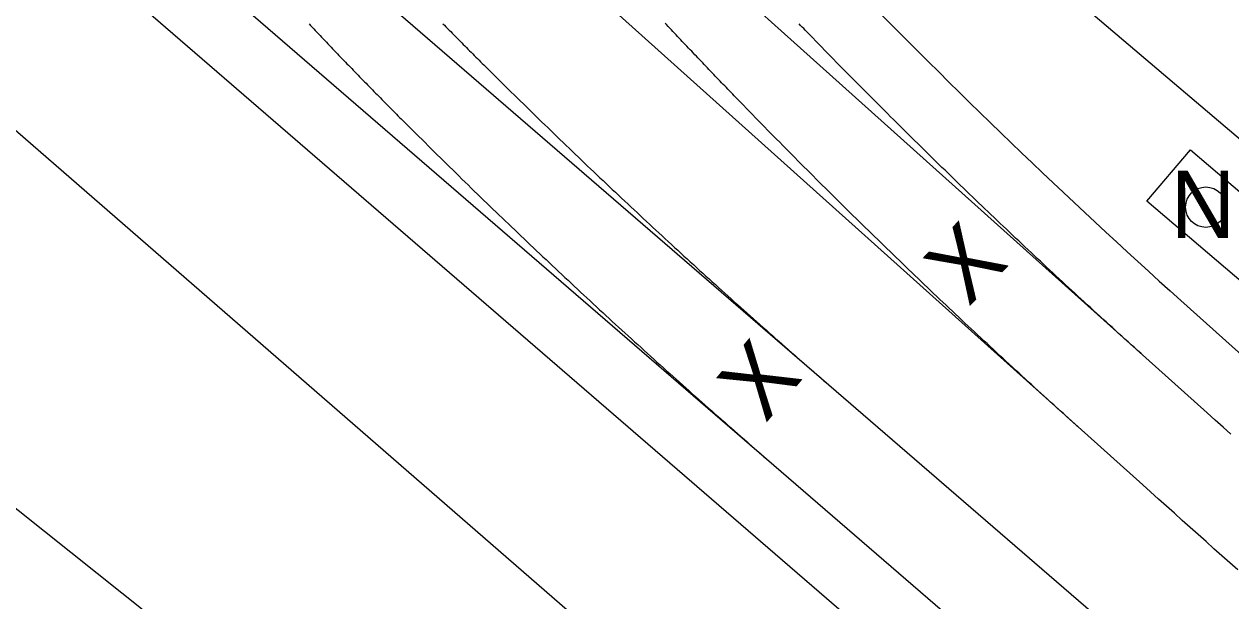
# Model space of a CAD drawing. Extents: x 81617 to 82144, y 454649 to 455150.
# Drawn here: x 81715.37 to 81733.29, y 454706.31 to 454714.88 of the extents above; entities that cross this region are included whole.
import ezdxf

# ---------------------------------------------------------------- set-up
doc = ezdxf.new("R2010")
doc.units = 0
doc.layers.add('B-WE-OG-TOPOGRAFIE-G', color=7, linetype='Continuous')
doc.layers.add('B-WE-VW-MARKERING-G', color=7, linetype='Continuous')

msp = doc.modelspace()

# ---------------------------------------------------------------- linework, layer by layer
at = {"layer": 'B-WE-OG-TOPOGRAFIE-G'}
for p, q in [((81703.871, 454726.575), (81730.855, 454703.267)), ((81735.247, 454708.351), (81732.548, 454710.771))]:
    msp.add_line(p, q, dxfattribs=at)
for points in [[(81733.293, 454708.784), (81733.175, 454708.889), (81733.058, 454708.994), (81732.94, 454709.1), (81732.94, 454709.1), (81698.035, 454740.405), (81698.035, 454740.405), (81697.901, 454740.525), (81697.766, 454740.646), (81697.632, 454740.766), (81697.498, 454740.887), (81697.364, 454741.007)], [(81733.393, 454706.767), (81733.276, 454706.872), (81733.158, 454706.977), (81733.04, 454707.083), (81732.923, 454707.188), (81732.805, 454707.294), (81732.688, 454707.399), (81732.57, 454707.504), (81732.452, 454707.61), (81732.335, 454707.715), (81732.217, 454707.821), (81732.1, 454707.926), (81731.982, 454708.032), (81731.982, 454708.032), (81697.077, 454739.337)], [(81711.061, 454723.559), (81760.224, 454681.093)], [(81710.123, 454722.473), (81759.251, 454680.037)], [(81704.937, 454722.283), (81708.662, 454719.021), (81727.987, 454702.211)], [(81735.955, 454711.019), (81730.684, 454715.496), (81729.646, 454716.37)], [(81719.598, 454714.878), (81719.621, 454714.854), (81719.644, 454714.829), (81719.668, 454714.804), (81719.691, 454714.779), (81719.714, 454714.755), (81719.738, 454714.73), (81719.761, 454714.705), (81719.784, 454714.681), (81719.808, 454714.656), (81719.831, 454714.631), (81719.855, 454714.607), (81719.878, 454714.582), (81719.902, 454714.558), (81719.925, 454714.533), (81719.948, 454714.509), (81719.972, 454714.484), (81719.995, 454714.46), (81720.019, 454714.435), (81720.042, 454714.411), (81720.066, 454714.386), (81720.089, 454714.362), (81720.113, 454714.337), (81720.137, 454714.313), (81720.16, 454714.288), (81720.184, 454714.264), (81720.207, 454714.24), (81720.231, 454714.215), (81720.254, 454714.191), (81720.278, 454714.167), (81720.302, 454714.142), (81720.325, 454714.118), (81720.349, 454714.094), (81720.373, 454714.07), (81720.396, 454714.045), (81720.42, 454714.021), (81720.444, 454713.997), (81720.467, 454713.973), (81720.491, 454713.948), (81720.515, 454713.924), (81720.539, 454713.9), (81720.562, 454713.876), (81720.586, 454713.852), (81720.61, 454713.828), (81720.634, 454713.804), (81720.657, 454713.78), (81720.681, 454713.755), (81720.705, 454713.731), (81720.729, 454713.707), (81720.752, 454713.683), (81720.776, 454713.659), (81720.8, 454713.635), (81720.824, 454713.611), (81720.848, 454713.587), (81720.872, 454713.563), (81720.895, 454713.539), (81720.919, 454713.515), (81720.943, 454713.491), (81720.967, 454713.468), (81720.991, 454713.444), (81721.015, 454713.42), (81721.039, 454713.396), (81721.063, 454713.372), (81721.087, 454713.348), (81721.11, 454713.324), (81721.134, 454713.3), (81721.158, 454713.277), (81721.182, 454713.253), (81721.206, 454713.229), (81721.23, 454713.205), (81721.23, 454713.205), (81721.276, 454713.16), (81721.321, 454713.115), (81721.367, 454713.07), (81721.412, 454713.024), (81721.458, 454712.979), (81721.503, 454712.934), (81721.549, 454712.889), (81721.595, 454712.844), (81721.64, 454712.799), (81721.686, 454712.755), (81721.732, 454712.71), (81721.778, 454712.665), (81721.823, 454712.62), (81721.869, 454712.575), (81721.915, 454712.53), (81721.961, 454712.486), (81722.007, 454712.441), (81722.053, 454712.396), (81722.099, 454712.352), (81722.145, 454712.307), (81722.191, 454712.262), (81722.237, 454712.218), (81722.283, 454712.173), (81722.329, 454712.129), (81722.375, 454712.084), (81722.422, 454712.04), (81722.468, 454711.996), (81722.514, 454711.951), (81722.56, 454711.907), (81722.607, 454711.863), (81722.653, 454711.818), (81722.699, 454711.774), (81722.746, 454711.73), (81722.792, 454711.686), (81722.838, 454711.641), (81722.885, 454711.597), (81722.931, 454711.553), (81722.978, 454711.509), (81723.024, 454711.465), (81723.071, 454711.421), (81723.118, 454711.377), (81723.164, 454711.333), (81723.211, 454711.289), (81723.258, 454711.245), (81723.304, 454711.201), (81723.351, 454711.157), (81723.398, 454711.114), (81723.445, 454711.07), (81723.492, 454711.026), (81723.538, 454710.982), (81723.585, 454710.939), (81723.632, 454710.895), (81723.679, 454710.851), (81723.726, 454710.808), (81723.773, 454710.764), (81723.82, 454710.72), (81723.867, 454710.677), (81723.914, 454710.633), (81723.961, 454710.59), (81724.008, 454710.547), (81724.056, 454710.503), (81724.103, 454710.46), (81724.15, 454710.416), (81724.197, 454710.373), (81724.244, 454710.33), (81724.292, 454710.287), (81724.339, 454710.243), (81724.386, 454710.2), (81724.434, 454710.157), (81724.481, 454710.114), (81724.529, 454710.071), (81724.576, 454710.028), (81724.624, 454709.985), (81724.671, 454709.942), (81724.719, 454709.899), (81724.766, 454709.856), (81724.814, 454709.813), (81724.861, 454709.77), (81724.909, 454709.727), (81724.957, 454709.684), (81725.005, 454709.641), (81725.052, 454709.599), (81725.1, 454709.556), (81725.148, 454709.513), (81725.196, 454709.471), (81725.243, 454709.428), (81725.291, 454709.385), (81725.339, 454709.343), (81725.387, 454709.3), (81725.435, 454709.258), (81725.483, 454709.215), (81725.531, 454709.173), (81725.579, 454709.13), (81725.627, 454709.088), (81725.675, 454709.045), (81725.723, 454709.003), (81725.772, 454708.961), (81725.82, 454708.919), (81725.868, 454708.876), (81725.916, 454708.834), (81725.964, 454708.792), (81726.013, 454708.75), (81726.061, 454708.708), (81726.109, 454708.665), (81726.158, 454708.623), (81726.206, 454708.581), (81726.254, 454708.539), (81726.303, 454708.497), (81726.351, 454708.455), (81726.4, 454708.414)], [(81721.585, 454714.882), (81721.609, 454714.859), (81721.632, 454714.835), (81721.655, 454714.811), (81721.679, 454714.788), (81721.702, 454714.764), (81721.725, 454714.74), (81721.749, 454714.717), (81721.772, 454714.693), (81721.795, 454714.67), (81721.819, 454714.646), (81721.842, 454714.622), (81721.866, 454714.599), (81721.889, 454714.575), (81721.912, 454714.552), (81721.936, 454714.528), (81721.959, 454714.505), (81721.983, 454714.481), (81722.006, 454714.458), (81722.03, 454714.434), (81722.053, 454714.411), (81722.077, 454714.387), (81722.1, 454714.364), (81722.124, 454714.34), (81722.147, 454714.317), (81722.171, 454714.293), (81722.195, 454714.27), (81722.218, 454714.246), (81722.242, 454714.223), (81722.242, 454714.223), (81722.287, 454714.178), (81722.331, 454714.134), (81722.376, 454714.089), (81722.421, 454714.045), (81722.466, 454714), (81722.511, 454713.956), (81722.556, 454713.912), (81722.601, 454713.867), (81722.646, 454713.823), (81722.691, 454713.779), (81722.736, 454713.734), (81722.782, 454713.69), (81722.827, 454713.646), (81722.872, 454713.602), (81722.917, 454713.558), (81722.962, 454713.514), (81723.008, 454713.47), (81723.053, 454713.426), (81723.098, 454713.382), (81723.144, 454713.338), (81723.189, 454713.294), (81723.234, 454713.25), (81723.28, 454713.206), (81723.325, 454713.162), (81723.371, 454713.118), (81723.416, 454713.074), (81723.462, 454713.031), (81723.507, 454712.987), (81723.553, 454712.943), (81723.599, 454712.899), (81723.644, 454712.856), (81723.69, 454712.812), (81723.736, 454712.768), (81723.781, 454712.725), (81723.827, 454712.681), (81723.873, 454712.638), (81723.919, 454712.594), (81723.965, 454712.551), (81724.011, 454712.507), (81724.057, 454712.464), (81724.102, 454712.421), (81724.148, 454712.377), (81724.194, 454712.334), (81724.24, 454712.291), (81724.287, 454712.247), (81724.333, 454712.204), (81724.379, 454712.161), (81724.425, 454712.118), (81724.471, 454712.075), (81724.517, 454712.032), (81724.563, 454711.989), (81724.61, 454711.945), (81724.656, 454711.902), (81724.702, 454711.859), (81724.749, 454711.816), (81724.795, 454711.774), (81724.841, 454711.731), (81724.888, 454711.688), (81724.934, 454711.645), (81724.981, 454711.602), (81725.027, 454711.559), (81725.074, 454711.517), (81725.12, 454711.474), (81725.167, 454711.431), (81725.213, 454711.389), (81725.26, 454711.346), (81725.307, 454711.303), (81725.353, 454711.261), (81725.4, 454711.218), (81725.447, 454711.176), (81725.493, 454711.133), (81725.54, 454711.091), (81725.587, 454711.048), (81725.634, 454711.006), (81725.681, 454710.963), (81725.728, 454710.921), (81725.775, 454710.879), (81725.821, 454710.837), (81725.868, 454710.794), (81725.915, 454710.752), (81725.962, 454710.71), (81726.01, 454710.668), (81726.057, 454710.626), (81726.104, 454710.584), (81726.151, 454710.541), (81726.198, 454710.499), (81726.245, 454710.457), (81726.292, 454710.415), (81726.34, 454710.373), (81726.387, 454710.332), (81726.434, 454710.29), (81726.482, 454710.248), (81726.529, 454710.206), (81726.576, 454710.164), (81726.624, 454710.122), (81726.671, 454710.081), (81726.719, 454710.039), (81726.766, 454709.997), (81726.814, 454709.956), (81726.861, 454709.914), (81726.909, 454709.872), (81726.956, 454709.831), (81727.004, 454709.789), (81727.051, 454709.748), (81727.099, 454709.706), (81727.147, 454709.665), (81727.195, 454709.624), (81727.242, 454709.582), (81727.29, 454709.541), (81727.338, 454709.499)], [(81731.042, 454708.875), (81730.994, 454708.918), (81730.946, 454708.961), (81730.899, 454709.004), (81730.851, 454709.047), (81730.803, 454709.089), (81730.756, 454709.132), (81730.708, 454709.175), (81730.661, 454709.218), (81730.613, 454709.262), (81730.566, 454709.305), (81730.518, 454709.348), (81730.471, 454709.391), (81730.424, 454709.434), (81730.376, 454709.477), (81730.329, 454709.52), (81730.282, 454709.564), (81730.234, 454709.607), (81730.187, 454709.65), (81730.14, 454709.694), (81730.093, 454709.737), (81730.046, 454709.78), (81729.999, 454709.824), (81729.951, 454709.867), (81729.904, 454709.911), (81729.857, 454709.954), (81729.81, 454709.998), (81729.763, 454710.042), (81729.716, 454710.085), (81729.669, 454710.129), (81729.623, 454710.173), (81729.576, 454710.216), (81729.529, 454710.26), (81729.482, 454710.304), (81729.435, 454710.348), (81729.388, 454710.391), (81729.342, 454710.435), (81729.295, 454710.479), (81729.248, 454710.523), (81729.202, 454710.567), (81729.155, 454710.611), (81729.108, 454710.655), (81729.062, 454710.699), (81729.015, 454710.743), (81728.969, 454710.787), (81728.922, 454710.831), (81728.876, 454710.875), (81728.83, 454710.92), (81728.783, 454710.964), (81728.737, 454711.008), (81728.69, 454711.052), (81728.644, 454711.097), (81728.598, 454711.141), (81728.552, 454711.185), (81728.505, 454711.23), (81728.459, 454711.274), (81728.413, 454711.319), (81728.367, 454711.363), (81728.321, 454711.408), (81728.275, 454711.452), (81728.229, 454711.497), (81728.182, 454711.541), (81728.136, 454711.586), (81728.091, 454711.631), (81728.045, 454711.675), (81727.999, 454711.72), (81727.953, 454711.765), (81727.907, 454711.81), (81727.861, 454711.854), (81727.815, 454711.899), (81727.769, 454711.944), (81727.724, 454711.989), (81727.678, 454712.034), (81727.632, 454712.079), (81727.587, 454712.124), (81727.541, 454712.169), (81727.495, 454712.214), (81727.45, 454712.259), (81727.404, 454712.304), (81727.359, 454712.349), (81727.313, 454712.394), (81727.268, 454712.439), (81727.222, 454712.485), (81727.177, 454712.53), (81727.132, 454712.575), (81727.086, 454712.62), (81727.041, 454712.666), (81726.996, 454712.711), (81726.95, 454712.756), (81726.905, 454712.802), (81726.86, 454712.847), (81726.815, 454712.893), (81726.77, 454712.938), (81726.725, 454712.984), (81726.679, 454713.029), (81726.634, 454713.075), (81726.589, 454713.121), (81726.544, 454713.166), (81726.499, 454713.212), (81726.455, 454713.258), (81726.41, 454713.303), (81726.365, 454713.349), (81726.32, 454713.395), (81726.275, 454713.441), (81726.23, 454713.486), (81726.185, 454713.532), (81726.141, 454713.578), (81726.096, 454713.624), (81726.051, 454713.67), (81726.007, 454713.716), (81725.962, 454713.762), (81725.962, 454713.762), (81725.938, 454713.786), (81725.915, 454713.811), (81725.891, 454713.835), (81725.868, 454713.859), (81725.844, 454713.884), (81725.821, 454713.908), (81725.797, 454713.933), (81725.774, 454713.957), (81725.75, 454713.981), (81725.727, 454714.006), (81725.703, 454714.03), (81725.68, 454714.055), (81725.656, 454714.079), (81725.633, 454714.103), (81725.61, 454714.128), (81725.586, 454714.152), (81725.563, 454714.177), (81725.539, 454714.201), (81725.516, 454714.226), (81725.492, 454714.25), (81725.469, 454714.275), (81725.446, 454714.299), (81725.422, 454714.324), (81725.399, 454714.349), (81725.375, 454714.373), (81725.352, 454714.398), (81725.329, 454714.422), (81725.305, 454714.447), (81725.282, 454714.472), (81725.259, 454714.496), (81725.235, 454714.521), (81725.212, 454714.546), (81725.189, 454714.57), (81725.166, 454714.595), (81725.142, 454714.62), (81725.119, 454714.644), (81725.096, 454714.669), (81725.072, 454714.694), (81725.049, 454714.719), (81725.026, 454714.743), (81725.003, 454714.768), (81724.98, 454714.793), (81724.956, 454714.818), (81724.933, 454714.843), (81724.91, 454714.868), (81724.887, 454714.892)], [(81732, 454709.943), (81731.953, 454709.986), (81731.906, 454710.028), (81731.859, 454710.07), (81731.812, 454710.112), (81731.765, 454710.155), (81731.718, 454710.197), (81731.671, 454710.239), (81731.624, 454710.282), (81731.578, 454710.324), (81731.531, 454710.367), (81731.484, 454710.409), (81731.437, 454710.452), (81731.391, 454710.494), (81731.344, 454710.537), (81731.297, 454710.58), (81731.251, 454710.622), (81731.204, 454710.665), (81731.158, 454710.708), (81731.111, 454710.75), (81731.064, 454710.793), (81731.018, 454710.836), (81730.972, 454710.879), (81730.925, 454710.922), (81730.879, 454710.964), (81730.832, 454711.007), (81730.786, 454711.05), (81730.74, 454711.093), (81730.693, 454711.136), (81730.647, 454711.179), (81730.601, 454711.222), (81730.555, 454711.265), (81730.509, 454711.309), (81730.462, 454711.352), (81730.416, 454711.395), (81730.37, 454711.438), (81730.324, 454711.481), (81730.278, 454711.525), (81730.232, 454711.568), (81730.186, 454711.611), (81730.14, 454711.655), (81730.094, 454711.698), (81730.048, 454711.741), (81730.002, 454711.785), (81729.957, 454711.828), (81729.911, 454711.872), (81729.865, 454711.915), (81729.819, 454711.959), (81729.773, 454712.002), (81729.728, 454712.046), (81729.682, 454712.09), (81729.636, 454712.133), (81729.591, 454712.177), (81729.545, 454712.221), (81729.5, 454712.264), (81729.454, 454712.308), (81729.408, 454712.352), (81729.363, 454712.396), (81729.318, 454712.44), (81729.272, 454712.484), (81729.227, 454712.528), (81729.181, 454712.572), (81729.136, 454712.616), (81729.091, 454712.66), (81729.045, 454712.704), (81729, 454712.748), (81728.955, 454712.792), (81728.91, 454712.836), (81728.864, 454712.88), (81728.819, 454712.924), (81728.774, 454712.969), (81728.729, 454713.013), (81728.684, 454713.057), (81728.639, 454713.101), (81728.594, 454713.146), (81728.549, 454713.19), (81728.504, 454713.234), (81728.459, 454713.279), (81728.414, 454713.323), (81728.369, 454713.368), (81728.325, 454713.412), (81728.28, 454713.457), (81728.235, 454713.501), (81728.19, 454713.546), (81728.145, 454713.591), (81728.101, 454713.635), (81728.056, 454713.68), (81728.011, 454713.725), (81727.967, 454713.769), (81727.922, 454713.814), (81727.878, 454713.859), (81727.833, 454713.904), (81727.789, 454713.949), (81727.744, 454713.994), (81727.7, 454714.038), (81727.655, 454714.083), (81727.611, 454714.128), (81727.567, 454714.173), (81727.522, 454714.218), (81727.478, 454714.263), (81727.434, 454714.308), (81727.389, 454714.354), (81727.345, 454714.399), (81727.301, 454714.444), (81727.257, 454714.489), (81727.213, 454714.534), (81727.169, 454714.579), (81727.125, 454714.625), (81727.081, 454714.67), (81727.037, 454714.715), (81726.993, 454714.761), (81726.992, 454714.761), (81726.969, 454714.785), (81726.946, 454714.809), (81726.923, 454714.833), (81726.9, 454714.857), (81726.877, 454714.881)], [(81732.693, 454713.006), (81734.896, 454711.133), (81734.248, 454710.371), (81732.045, 454712.244), (81732.693, 454713.006)]]:
    msp.add_lwpolyline(points, dxfattribs=at)
msp.add_circle((81732.92, 454712.157), 0.3, dxfattribs=at)
msp.add_arc((81798.18, 454783.952), 98.3, 224.1019, 228.11261, dxfattribs=at)
at = {"layer": 'B-WE-VW-MARKERING-G'}
msp.add_lwpolyline([(81754.205, 454674.562), (81750.269, 454678.038), (81736.422, 454689.987), (81726.94, 454698.352), (81714.491, 454708.275)], dxfattribs=at)

# ---------------------------------------------------------------- texts
at = {"layer": 'B-WE-OG-TOPOGRAFIE-G'}
msp.add_text('N', height=1, dxfattribs=at).set_placement((81732.394, 454711.7))
for rotation, p in [(46.1782, (81729.393, 454710.665)), (50.359, (81726.377, 454708.935))]:
    msp.add_text('X', height=1, rotation=rotation, dxfattribs=at).set_placement(p)

doc.saveas('drawing.dxf')
